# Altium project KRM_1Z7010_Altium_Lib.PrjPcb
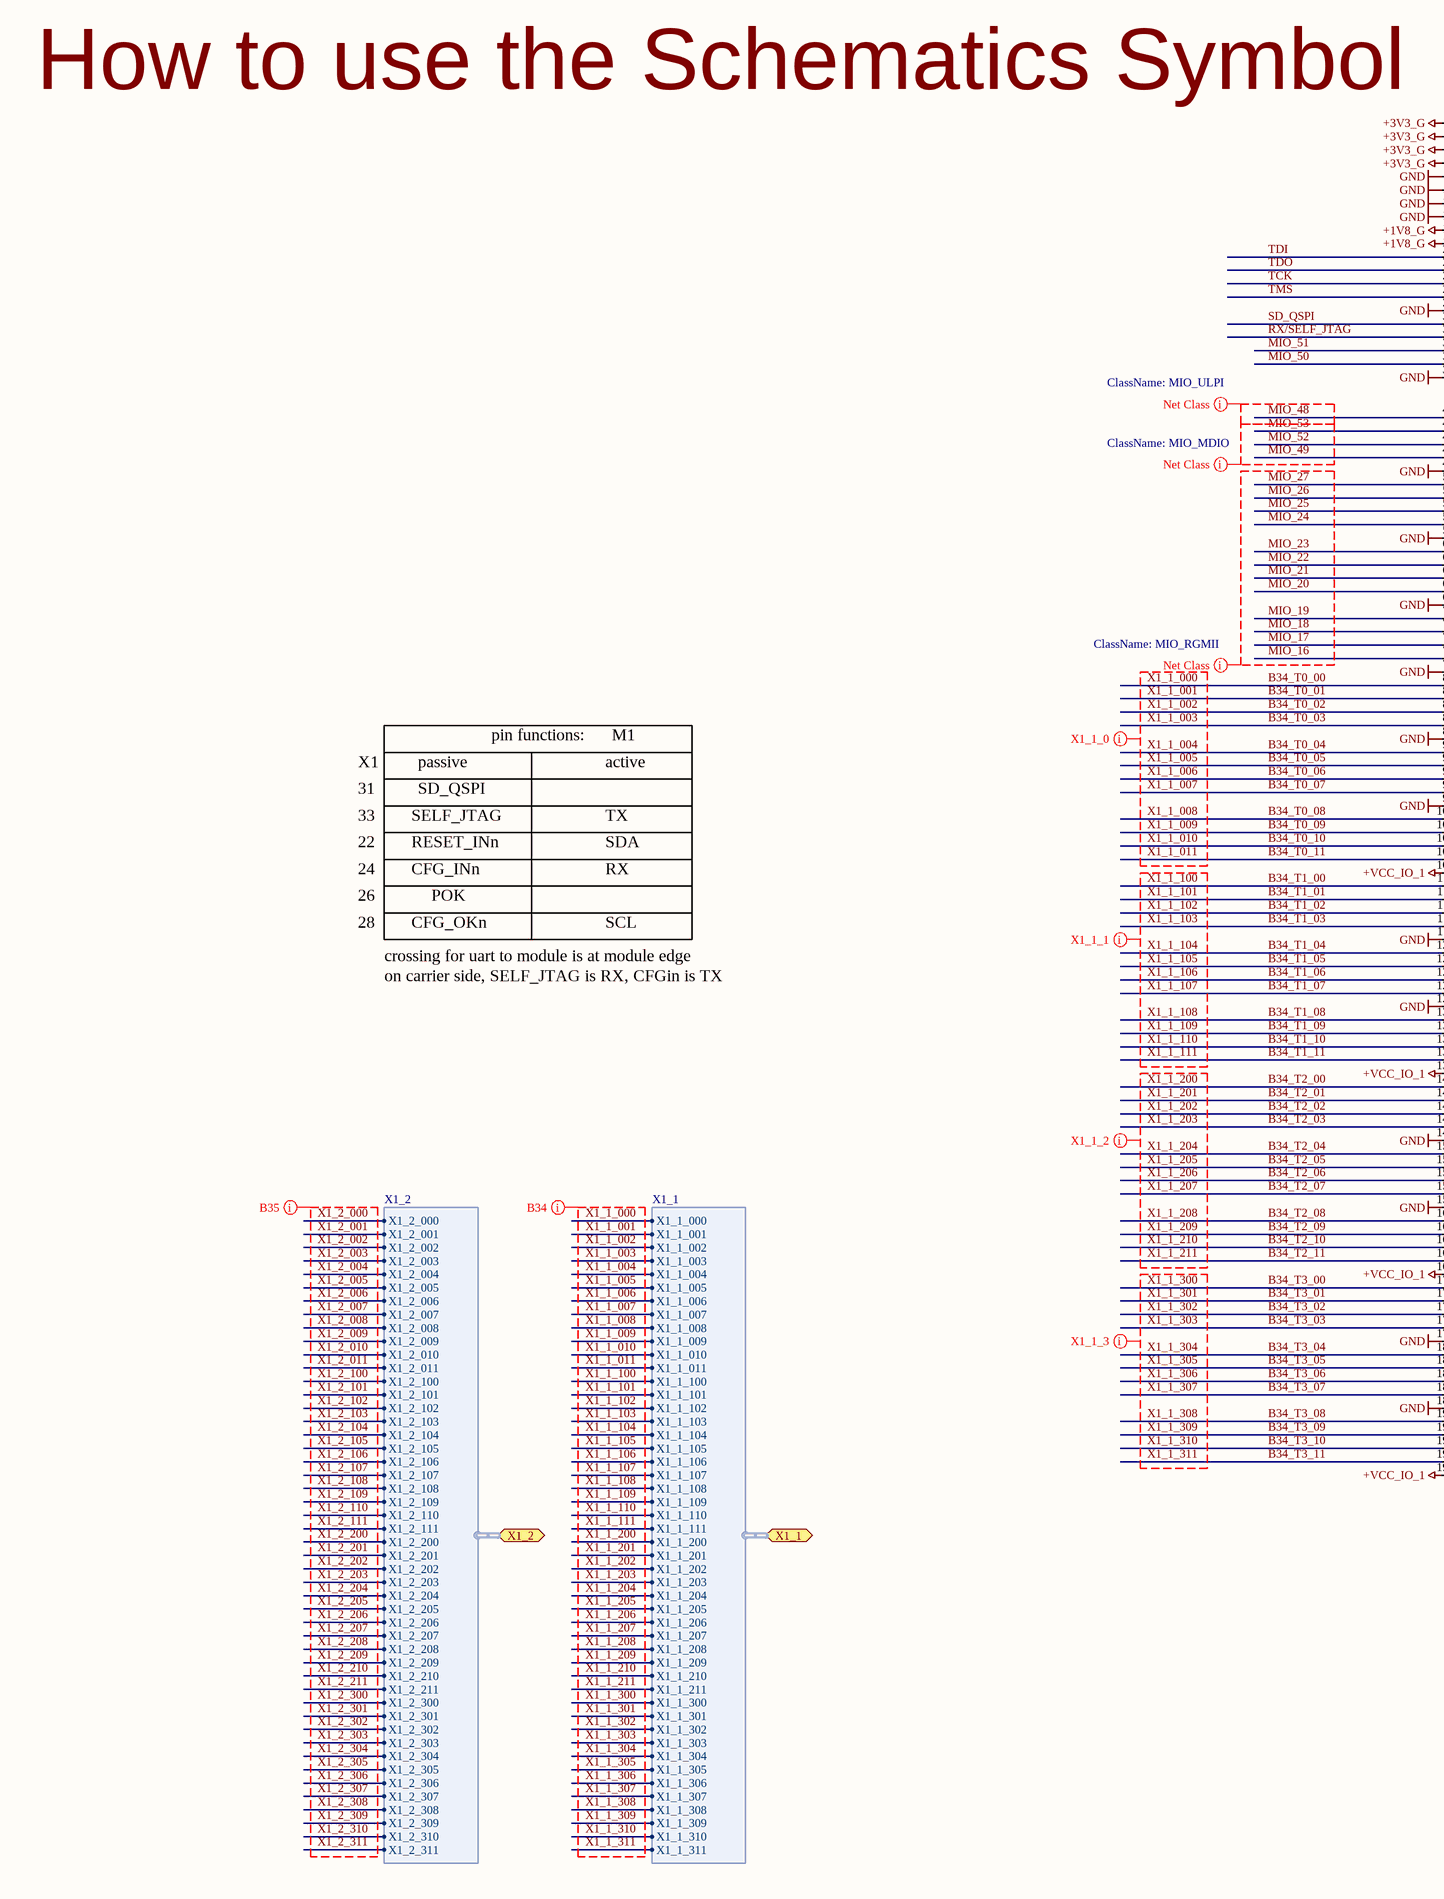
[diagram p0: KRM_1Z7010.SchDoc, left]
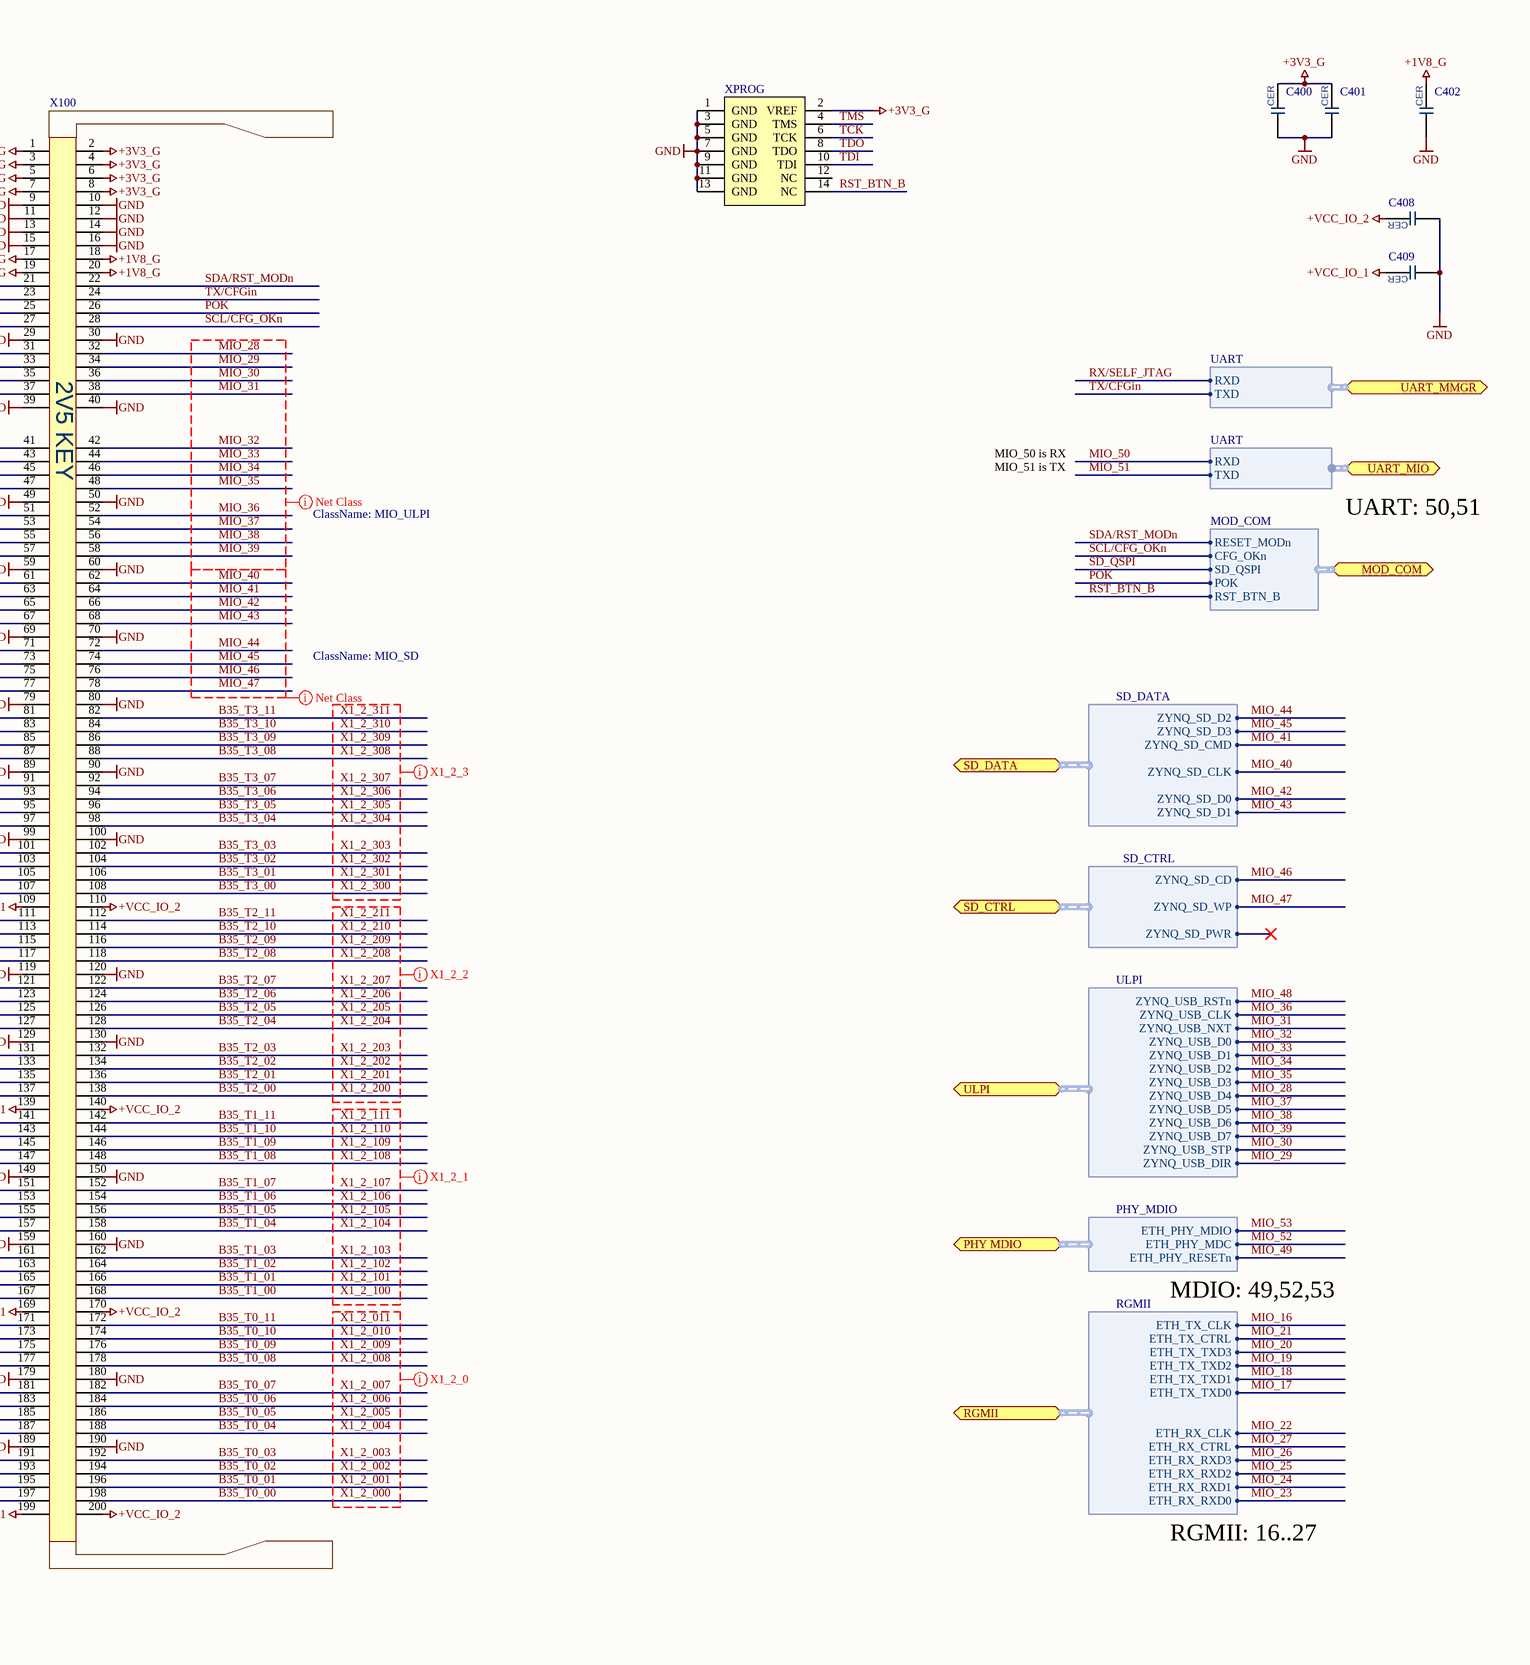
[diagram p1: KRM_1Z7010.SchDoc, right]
Project_Title: KRM-1Z7010 Template Project
1 sheet, 7 parts. Net scope: flat (ports and power ports of the same name join across sheets).

## Sheet KRM_1Z7010.SchDoc: KRM-1Z7010 Module Symbols
size A2; Project: KRM1711 CARRIER; ApprovedBy: _not used_; CheckedBy: _not used_; Author: KR/xx; CompanyName: _not used_; DrawnBy: _not used_; Engineer: _not used_; Organization: Knowledge Resources GmbH; Address1: Ackerstrasse 30; Address2: 4057 Basel, Switzerland; Address3: www.knowres.com; DocumentNumber: _tbd_; Revision: _not used_; SheetNumber: _tbd_; SheetTotal: _tbd_

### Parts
C400  C_KERAMIK  [C0603_H]  (value not drawn)
C401  C_KERAMIK  [C0603_H]  (value not drawn)
C402  C_KERAMIK  [C0603_H]  (value not drawn)
C408  C_KERAMIK  [C0603_H]  (value not drawn)
C409  C_KERAMIK  [C0603_H]  (value not drawn)
X100  X_SO_DIMM_200_2V5  [DDR1_SODIMM]  (value not drawn)
XPROG  X_XILINX_JTAG_HEADER  [X_2X7_2_SMD_M_WO_BG]  (value not drawn)

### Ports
MOD_COM (harness MOD_COM), PHY MDIO (harness PHY_MDIO), RGMII (harness RGMII), SD_CTRL (harness SD_CTRL), SD_DATA (harness SD_DATA), UART_MIO (harness UART), UART_MMGR (harness UART), ULPI (harness ULPI), X1_1 (harness X1_1), X1_2 (harness X1_2)

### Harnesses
SD_DATA: ZYNQ_SD_D2, ZYNQ_SD_D3, ZYNQ_SD_CMD, ZYNQ_SD_CLK, ZYNQ_SD_D0, ZYNQ_SD_D1
ULPI: ZYNQ_USB_CLK, ZYNQ_USB_NXT, ZYNQ_USB_D0, ZYNQ_USB_D1, ZYNQ_USB_D2, ZYNQ_USB_D3, ZYNQ_USB_D4, ZYNQ_USB_D5, ZYNQ_USB_D6, ZYNQ_USB_D7, ZYNQ_USB_STP, ZYNQ_USB_DIR, ZYNQ_USB_RSTn
RGMII: ETH_TX_TXD3, ETH_TX_TXD2, ETH_TX_CLK, ETH_TX_CTRL, ETH_TX_TXD1, ETH_TX_TXD0, ETH_RX_CLK, ETH_RX_CTRL, ETH_RX_RXD3, ETH_RX_RXD2, ETH_RX_RXD1, ETH_RX_RXD0
PHY_MDIO: ETH_PHY_MDIO, ETH_PHY_MDC, ETH_PHY_RESETn
X1_2: X1_2_000, X1_2_001, X1_2_002, X1_2_003, X1_2_004, X1_2_005, X1_2_006, X1_2_007, X1_2_008, X1_2_009, X1_2_010, X1_2_011, X1_2_100, X1_2_101, X1_2_102, X1_2_103, X1_2_104, X1_2_105, X1_2_106, X1_2_107, X1_2_108, X1_2_109, X1_2_110, X1_2_111, X1_2_200, X1_2_201, X1_2_202, X1_2_203, X1_2_204, X1_2_205, X1_2_206, X1_2_207, X1_2_208, X1_2_209, X1_2_210, X1_2_211, X1_2_300, X1_2_301, X1_2_302, X1_2_303, X1_2_304, X1_2_305, X1_2_306, X1_2_307, X1_2_308, X1_2_309, X1_2_310, X1_2_311
X1_1: X1_1_000, X1_1_001, X1_1_002, X1_1_003, X1_1_004, X1_1_005, X1_1_006, X1_1_007, X1_1_008, X1_1_009, X1_1_010, X1_1_011, X1_1_100, X1_1_101, X1_1_102, X1_1_103, X1_1_104, X1_1_105, X1_1_106, X1_1_107, X1_1_108, X1_1_109, X1_1_110, X1_1_111, X1_1_200, X1_1_201, X1_1_202, X1_1_203, X1_1_204, X1_1_205, X1_1_206, X1_1_207, X1_1_208, X1_1_209, X1_1_210, X1_1_211, X1_1_300, X1_1_301, X1_1_302, X1_1_303, X1_1_304, X1_1_305, X1_1_306, X1_1_307, X1_1_308, X1_1_309, X1_1_310, X1_1_311
MOD_COM: RESET_MODn, CFG_OKn, SD_QSPI, POK, RST_BTN_B
UART: RXD, TXD
SD_CTRL: ZYNQ_SD_CD, ZYNQ_SD_WP, ZYNQ_SD_PWR

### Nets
+1V8_G: C402.1 X100.17 X100.18 X100.19 X100.20
+3V3_G: C400.1 C401.1 X100.1 X100.2 X100.3 X100.4 X100.5 X100.6 X100.7 X100.8 XPROG.2(VREF)
+VCC_IO_1: C409.1 X100.109 X100.139 X100.169 X100.199
+VCC_IO_2: C408.1 X100.110 X100.140 X100.170 X100.200
GND: C400.2 C401.2 C402.2 C408.2 C409.2 X100.9 X100.10 X100.11 X100.12 X100.13 X100.14 X100.15 X100.16 X100.29 X100.30 X100.39 X100.40 X100.49 X100.50 X100.59 X100.60 X100.69 X100.70 X100.79 X100.80 X100.89 X100.90 X100.99 X100.100 X100.119 X100.120 X100.129 X100.130 X100.149 X100.150 X100.159 X100.160 X100.179 X100.180 X100.189 X100.190 XPROG.1(GND) XPROG.3(GND) XPROG.5(GND) XPROG.7(GND) XPROG.9(GND) XPROG.11(GND) XPROG.13(GND)
B34_T0_00: X100.81 ; port X1_1.X1_1_000  [also labelled X1_1_000]
B34_T0_01: X100.83 ; port X1_1.X1_1_001  [also labelled X1_1_001]
B34_T0_02: X100.85 ; port X1_1.X1_1_002  [also labelled X1_1_002]
B34_T0_03: X100.87 ; port X1_1.X1_1_003  [also labelled X1_1_003]
B34_T0_04: X100.91 ; port X1_1.X1_1_004  [also labelled X1_1_004]
B34_T0_05: X100.93 ; port X1_1.X1_1_005  [also labelled X1_1_005]
B34_T0_06: X100.95 ; port X1_1.X1_1_006  [also labelled X1_1_006]
B34_T0_07: X100.97 ; port X1_1.X1_1_007  [also labelled X1_1_007]
B34_T0_08: X100.101 ; port X1_1.X1_1_008  [also labelled X1_1_008]
B34_T0_09: X100.103 ; port X1_1.X1_1_009  [also labelled X1_1_009]
B34_T0_10: X100.105 ; port X1_1.X1_1_010  [also labelled X1_1_010]
B34_T0_11: X100.107 ; port X1_1.X1_1_011  [also labelled X1_1_011]
B34_T1_00: X100.111 ; port X1_1.X1_1_100  [also labelled X1_1_100]
B34_T1_01: X100.113 ; port X1_1.X1_1_101  [also labelled X1_1_101]
B34_T1_02: X100.115 ; port X1_1.X1_1_102  [also labelled X1_1_102]
B34_T1_03: X100.117 ; port X1_1.X1_1_103  [also labelled X1_1_103]
B34_T1_04: X100.121 ; port X1_1.X1_1_104  [also labelled X1_1_104]
B34_T1_05: X100.123 ; port X1_1.X1_1_105  [also labelled X1_1_105]
B34_T1_06: X100.125 ; port X1_1.X1_1_106  [also labelled X1_1_106]
B34_T1_07: X100.127 ; port X1_1.X1_1_107  [also labelled X1_1_107]
B34_T1_08: X100.131 ; port X1_1.X1_1_108  [also labelled X1_1_108]
B34_T1_09: X100.133 ; port X1_1.X1_1_109  [also labelled X1_1_109]
B34_T1_10: X100.135 ; port X1_1.X1_1_110  [also labelled X1_1_110]
B34_T1_11: X100.137 ; port X1_1.X1_1_111  [also labelled X1_1_111]
B34_T2_00: X100.141 ; port X1_1.X1_1_200  [also labelled X1_1_200]
B34_T2_01: X100.143 ; port X1_1.X1_1_201  [also labelled X1_1_201]
B34_T2_02: X100.145 ; port X1_1.X1_1_202  [also labelled X1_1_202]
B34_T2_03: X100.147 ; port X1_1.X1_1_203  [also labelled X1_1_203]
B34_T2_04: X100.151 ; port X1_1.X1_1_204  [also labelled X1_1_204]
B34_T2_05: X100.153 ; port X1_1.X1_1_205  [also labelled X1_1_205]
B34_T2_06: X100.155 ; port X1_1.X1_1_206  [also labelled X1_1_206]
B34_T2_07: X100.157 ; port X1_1.X1_1_207  [also labelled X1_1_207]
B34_T2_08: X100.161 ; port X1_1.X1_1_208  [also labelled X1_1_208]
B34_T2_09: X100.163 ; port X1_1.X1_1_209  [also labelled X1_1_209]
B34_T2_10: X100.165 ; port X1_1.X1_1_210  [also labelled X1_1_210]
B34_T2_11: X100.167 ; port X1_1.X1_1_211  [also labelled X1_1_211]
B34_T3_00: X100.171 ; port X1_1.X1_1_300  [also labelled X1_1_300]
B34_T3_01: X100.173 ; port X1_1.X1_1_301  [also labelled X1_1_301]
B34_T3_02: X100.175 ; port X1_1.X1_1_302  [also labelled X1_1_302]
B34_T3_03: X100.177 ; port X1_1.X1_1_303  [also labelled X1_1_303]
B34_T3_04: X100.181 ; port X1_1.X1_1_304  [also labelled X1_1_304]
B34_T3_05: X100.183 ; port X1_1.X1_1_305  [also labelled X1_1_305]
B34_T3_06: X100.185 ; port X1_1.X1_1_306  [also labelled X1_1_306]
B34_T3_07: X100.187 ; port X1_1.X1_1_307  [also labelled X1_1_307]
B34_T3_08: X100.191 ; port X1_1.X1_1_308  [also labelled X1_1_308]
B34_T3_09: X100.193 ; port X1_1.X1_1_309  [also labelled X1_1_309]
B34_T3_10: X100.195 ; port X1_1.X1_1_310  [also labelled X1_1_310]
B34_T3_11: X100.197 ; port X1_1.X1_1_311  [also labelled X1_1_311]
B35_T0_00: X100.198 ; port X1_2.X1_2_000  [also labelled X1_2_000]
B35_T0_01: X100.196 ; port X1_2.X1_2_001  [also labelled X1_2_001]
B35_T0_02: X100.194 ; port X1_2.X1_2_002  [also labelled X1_2_002]
B35_T0_03: X100.192 ; port X1_2.X1_2_003  [also labelled X1_2_003]
B35_T0_04: X100.188 ; port X1_2.X1_2_004  [also labelled X1_2_004]
B35_T0_05: X100.186 ; port X1_2.X1_2_005  [also labelled X1_2_005]
B35_T0_06: X100.184 ; port X1_2.X1_2_006  [also labelled X1_2_006]
B35_T0_07: X100.182 ; port X1_2.X1_2_007  [also labelled X1_2_007]
B35_T0_08: X100.178 ; port X1_2.X1_2_008  [also labelled X1_2_008]
B35_T0_09: X100.176 ; port X1_2.X1_2_009  [also labelled X1_2_009]
B35_T0_10: X100.174 ; port X1_2.X1_2_010  [also labelled X1_2_010]
B35_T0_11: X100.172 ; port X1_2.X1_2_011  [also labelled X1_2_011]
B35_T1_00: X100.168 ; port X1_2.X1_2_100  [also labelled X1_2_100]
B35_T1_01: X100.166 ; port X1_2.X1_2_101  [also labelled X1_2_101]
B35_T1_02: X100.164 ; port X1_2.X1_2_102  [also labelled X1_2_102]
B35_T1_03: X100.162 ; port X1_2.X1_2_103  [also labelled X1_2_103]
B35_T1_04: X100.158 ; port X1_2.X1_2_104  [also labelled X1_2_104]
B35_T1_05: X100.156 ; port X1_2.X1_2_105  [also labelled X1_2_105]
B35_T1_06: X100.154 ; port X1_2.X1_2_106  [also labelled X1_2_106]
B35_T1_07: X100.152 ; port X1_2.X1_2_107  [also labelled X1_2_107]
B35_T1_08: X100.148 ; port X1_2.X1_2_108  [also labelled X1_2_108]
B35_T1_09: X100.146 ; port X1_2.X1_2_109  [also labelled X1_2_109]
B35_T1_10: X100.144 ; port X1_2.X1_2_110  [also labelled X1_2_110]
B35_T1_11: X100.142 ; port X1_2.X1_2_111  [also labelled X1_2_111]
B35_T2_00: X100.138 ; port X1_2.X1_2_200  [also labelled X1_2_200]
B35_T2_01: X100.136 ; port X1_2.X1_2_201  [also labelled X1_2_201]
B35_T2_02: X100.134 ; port X1_2.X1_2_202  [also labelled X1_2_202]
B35_T2_03: X100.132 ; port X1_2.X1_2_203  [also labelled X1_2_203]
B35_T2_04: X100.128 ; port X1_2.X1_2_204  [also labelled X1_2_204]
B35_T2_05: X100.126 ; port X1_2.X1_2_205  [also labelled X1_2_205]
B35_T2_06: X100.124 ; port X1_2.X1_2_206  [also labelled X1_2_206]
B35_T2_07: X100.122 ; port X1_2.X1_2_207  [also labelled X1_2_207]
B35_T2_08: X100.118 ; port X1_2.X1_2_208  [also labelled X1_2_208]
B35_T2_09: X100.116 ; port X1_2.X1_2_209  [also labelled X1_2_209]
B35_T2_10: X100.114 ; port X1_2.X1_2_210  [also labelled X1_2_210]
B35_T2_11: X100.112 ; port X1_2.X1_2_211  [also labelled X1_2_211]
B35_T3_00: X100.108 ; port X1_2.X1_2_300  [also labelled X1_2_300]
B35_T3_01: X100.106 ; port X1_2.X1_2_301  [also labelled X1_2_301]
B35_T3_02: X100.104 ; port X1_2.X1_2_302  [also labelled X1_2_302]
B35_T3_03: X100.102 ; port X1_2.X1_2_303  [also labelled X1_2_303]
B35_T3_04: X100.98 ; port X1_2.X1_2_304  [also labelled X1_2_304]
B35_T3_05: X100.96 ; port X1_2.X1_2_305  [also labelled X1_2_305]
B35_T3_06: X100.94 ; port X1_2.X1_2_306  [also labelled X1_2_306]
B35_T3_07: X100.92 ; port X1_2.X1_2_307  [also labelled X1_2_307]
B35_T3_08: X100.88 ; port X1_2.X1_2_308  [also labelled X1_2_308]
B35_T3_09: X100.86 ; port X1_2.X1_2_309  [also labelled X1_2_309]
B35_T3_10: X100.84 ; port X1_2.X1_2_310  [also labelled X1_2_310]
B35_T3_11: X100.82 ; port X1_2.X1_2_311  [also labelled X1_2_311]
MIO_16: X100.77 ; port RGMII.ETH_TX_CLK
MIO_17: X100.75 ; port RGMII.ETH_TX_TXD0
MIO_18: X100.73 ; port RGMII.ETH_TX_TXD1
MIO_19: X100.71 ; port RGMII.ETH_TX_TXD2
MIO_20: X100.67 ; port RGMII.ETH_TX_TXD3
MIO_21: X100.65 ; port RGMII.ETH_TX_CTRL
MIO_22: X100.63 ; port RGMII.ETH_RX_CLK
MIO_23: X100.61 ; port RGMII.ETH_RX_RXD0
MIO_24: X100.57 ; port RGMII.ETH_RX_RXD1
MIO_25: X100.55 ; port RGMII.ETH_RX_RXD2
MIO_26: X100.53 ; port RGMII.ETH_RX_RXD3
MIO_27: X100.51 ; port RGMII.ETH_RX_CTRL
MIO_28: X100.32 ; port ULPI.ZYNQ_USB_D4
MIO_29: X100.34 ; port ULPI.ZYNQ_USB_DIR
MIO_30: X100.36 ; port ULPI.ZYNQ_USB_STP
MIO_31: X100.38 ; port ULPI.ZYNQ_USB_NXT
MIO_32: X100.42 ; port ULPI.ZYNQ_USB_D0
MIO_33: X100.44 ; port ULPI.ZYNQ_USB_D1
MIO_34: X100.46 ; port ULPI.ZYNQ_USB_D2
MIO_35: X100.48 ; port ULPI.ZYNQ_USB_D3
MIO_36: X100.52 ; port ULPI.ZYNQ_USB_CLK
MIO_37: X100.54 ; port ULPI.ZYNQ_USB_D5
MIO_38: X100.56 ; port ULPI.ZYNQ_USB_D6
MIO_39: X100.58 ; port ULPI.ZYNQ_USB_D7
MIO_40: X100.62 ; port SD_DATA.ZYNQ_SD_CLK
MIO_41: X100.64 ; port SD_DATA.ZYNQ_SD_CMD
MIO_42: X100.66 ; port SD_DATA.ZYNQ_SD_D0
MIO_43: X100.68 ; port SD_DATA.ZYNQ_SD_D1
MIO_44: X100.72 ; port SD_DATA.ZYNQ_SD_D2
MIO_45: X100.74 ; port SD_DATA.ZYNQ_SD_D3
MIO_46: X100.76 ; port SD_CTRL.ZYNQ_SD_CD
MIO_47: X100.78 ; port SD_CTRL.ZYNQ_SD_WP
MIO_48: X100.41 ; port ULPI.ZYNQ_USB_RSTn
MIO_49: X100.47 ; port PHY MDIO.ETH_PHY_RESETn
MIO_50: X100.37 ; port UART_MIO.RXD
MIO_51: X100.35 ; port UART_MIO.TXD
MIO_52: X100.45 ; port PHY MDIO.ETH_PHY_MDC
MIO_53: X100.43 ; port PHY MDIO.ETH_PHY_MDIO
POK: X100.26 ; port MOD_COM.POK
RST_BTN_B: XPROG.14(NC) ; port MOD_COM.RST_BTN_B
RX/SELF_JTAG: X100.33 ; port UART_MMGR.RXD
SCL/CFG_OKn: X100.28 ; port MOD_COM.CFG_OKn
SD_QSPI: X100.31 ; port MOD_COM.SD_QSPI
SDA/RST_MODn: X100.22 ; port MOD_COM.RESET_MODn
TCK: X100.25 XPROG.6(TCK)
TDI: X100.21 XPROG.10(TDI)
TDO: X100.23 XPROG.8(TDO)
TMS: X100.27 XPROG.4(TMS)
TX/CFGin: X100.24 ; port UART_MMGR.TXD

Not connected (* = marked no-connect by the designer): XPROG 12(NC)

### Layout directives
net class X1_2_1: X1_2_100, X1_2_101, X1_2_102, X1_2_103, X1_2_104, X1_2_105, X1_2_106, X1_2_107, X1_2_108, X1_2_109, X1_2_110, X1_2_111
net class X1_2_3: X1_2_300, X1_2_301, X1_2_302, X1_2_303, X1_2_304, X1_2_305, X1_2_306, X1_2_307, X1_2_308, X1_2_309, X1_2_310, X1_2_311
net class X1_1_1: X1_1_100, X1_1_101, X1_1_102, X1_1_103, X1_1_104, X1_1_105, X1_1_106, X1_1_107, X1_1_108, X1_1_109, X1_1_110, X1_1_111
net class X1_1_3: X1_1_300, X1_1_301, X1_1_302, X1_1_303, X1_1_304, X1_1_305, X1_1_306, X1_1_307, X1_1_308, X1_1_309, X1_1_310, X1_1_311
net class X1_2_0: X1_2_000, X1_2_001, X1_2_002, X1_2_003, X1_2_004, X1_2_005, X1_2_006, X1_2_007, X1_2_008, X1_2_009, X1_2_010, X1_2_011
net class X1_2_2: X1_2_200, X1_2_201, X1_2_202, X1_2_203, X1_2_204, X1_2_205, X1_2_206, X1_2_207, X1_2_208, X1_2_209, X1_2_210, X1_2_211
net class X1_1_0: X1_1_000, X1_1_001, X1_1_002, X1_1_003, X1_1_004, X1_1_005, X1_1_006, X1_1_007, X1_1_008, X1_1_009, X1_1_010, X1_1_011
net class X1_1_2: X1_1_200, X1_1_201, X1_1_202, X1_1_203, X1_1_204, X1_1_205, X1_1_206, X1_1_207, X1_1_208, X1_1_209, X1_1_210, X1_1_211
net class MIO_RGMII: MIO_16, MIO_17, MIO_18, MIO_19, MIO_20, MIO_21, MIO_22, MIO_23, MIO_24, MIO_25, MIO_26, MIO_27
net class MIO_ULPI: MIO_28, MIO_29, MIO_30, MIO_31, MIO_32, MIO_33, MIO_34, MIO_35, MIO_36, MIO_37, MIO_38, MIO_39, MIO_48
net class MIO_MDIO: MIO_49, MIO_52, MIO_53
net class MIO_SD: MIO_40, MIO_41, MIO_42, MIO_43, MIO_44, MIO_45, MIO_46, MIO_47
net class B35: X1_2_000, X1_2_001, X1_2_002, X1_2_003, X1_2_004, X1_2_005, X1_2_006, X1_2_007, X1_2_008, X1_2_009, X1_2_010, X1_2_011, X1_2_100, X1_2_101, X1_2_102, X1_2_103, X1_2_104, X1_2_105, X1_2_106, X1_2_107, X1_2_108, X1_2_109, X1_2_110, X1_2_111, X1_2_200, X1_2_201, X1_2_202, X1_2_203, X1_2_204, X1_2_205, X1_2_206, X1_2_207, X1_2_208, X1_2_209, X1_2_210, X1_2_211, X1_2_300, X1_2_301, X1_2_302, X1_2_303, X1_2_304, X1_2_305, X1_2_306, X1_2_307, X1_2_308, X1_2_309, X1_2_310, X1_2_311
net class B34: X1_1_000, X1_1_001, X1_1_002, X1_1_003, X1_1_004, X1_1_005, X1_1_006, X1_1_007, X1_1_008, X1_1_009, X1_1_010, X1_1_011, X1_1_100, X1_1_101, X1_1_102, X1_1_103, X1_1_104, X1_1_105, X1_1_106, X1_1_107, X1_1_108, X1_1_109, X1_1_110, X1_1_111, X1_1_200, X1_1_201, X1_1_202, X1_1_203, X1_1_204, X1_1_205, X1_1_206, X1_1_207, X1_1_208, X1_1_209, X1_1_210, X1_1_211, X1_1_300, X1_1_301, X1_1_302, X1_1_303, X1_1_304, X1_1_305, X1_1_306, X1_1_307, X1_1_308, X1_1_309, X1_1_310, X1_1_311

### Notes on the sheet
- (near X100) How to use the Schematics Symbol
- MIO_50 is RX
- MIO_51 is TX
- UART: 50,51
- pin functions:
- M1
- 31
- X1
- passive
- SD_QSPI
- active
- 22
- 24
- 33
- SELF_JTAG
- RESET_INn
- CFG_INn
- SDA
- TX
- RX
- 26
- 28
- CFG_OKn
- POK
- SCL
- crossing for uart to module is at module edge
- on carrier side, SELF_JTAG is RX, CFGin is TX
- MDIO: 49,52,53
- RGMII: 16..27

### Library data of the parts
C400-C402 C408 C409 = 1568: Mfgr_Part: CL10A226MR8NQDC; Manufacturer: Samsung Electro-Mechanics Inc.
X100 = 1285: 200PIN SO DIMM DDR1 SOCKET 5.2MM R/A; Mfgr_Part: 1473005-1; Manufacturer: TE Connectivity
XPROG = 1010: 14PIN 2mm VERT SHROUDED LOCATOR; MANUFACTURER: Molex Connector Corporation; Mfgr_Part: 0878321416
